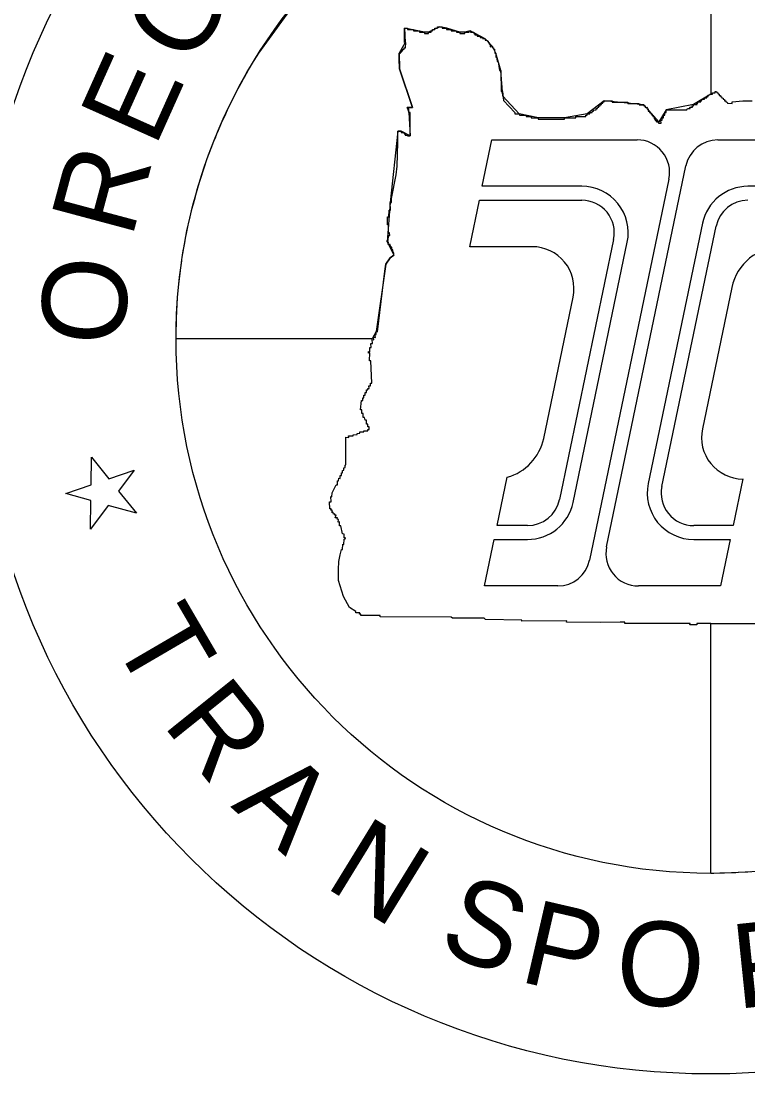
# Model space of a CAD drawing. Extents: x -1.2 to 17.3, y -1 to 2.5.
# Drawn here: x 16.5114 to 16.5609, y 1.8417 to 1.9133 of the extents above; entities that cross this region are included whole.
import ezdxf

# ---------------------------------------------------------------- set-up
doc = ezdxf.new("R2010")
doc.units = 0
doc.layers.add('P_ODOT_PLAN_TBlock', color=7, linetype='Continuous')

msp = doc.modelspace()

# ---------------------------------------------------------------- linework, layer by layer
at = {"layer": 'P_ODOT_PLAN_TBlock'}
for p, q in [((16.542797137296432, 1.9020324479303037), (16.543455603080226, 1.905192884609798)), ((16.543455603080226, 1.905192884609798), (16.55332512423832, 1.905192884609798)), ((16.55881333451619, 1.905192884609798), (16.57758831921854, 1.905192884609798)), ((16.5512484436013, 1.877516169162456), (16.55664756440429, 1.903431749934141)), ((16.549563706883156, 1.9020324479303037), (16.542797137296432, 1.9020324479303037)), ((16.55549089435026, 1.9025294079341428), (16.550092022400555, 1.8766138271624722)), ((16.57692985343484, 1.9020324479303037), (16.56086264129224, 1.9020324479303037)), ((16.541941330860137, 1.8979238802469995), (16.54259979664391, 1.901084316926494)), ((16.54259979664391, 1.901084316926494), (16.549563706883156, 1.901084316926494)), ((16.55776864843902, 1.8995165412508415), (16.554081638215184, 1.8818180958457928)), ((16.555009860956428, 1.8816247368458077), (16.558697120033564, 1.8993231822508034)), ((16.55172947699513, 1.898420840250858), (16.5480424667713, 1.8807223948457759)), ((16.54619099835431, 1.8979238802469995), (16.541941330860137, 1.8979238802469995)), ((16.54619099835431, 1.8979238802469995), (16.54619099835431, 1.8979238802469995)), ((16.548970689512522, 1.8805290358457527), (16.552657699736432, 1.8982274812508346)), ((16.559765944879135, 1.8951563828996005), (16.557763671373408, 1.8855461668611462)), ((16.546973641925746, 1.8848891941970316), (16.54897566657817, 1.8944994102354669)), ((16.54380175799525, 1.8789612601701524), (16.544486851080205, 1.8822498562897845)), ((16.56051573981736, 1.8821284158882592), (16.559855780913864, 1.8789612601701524)), ((16.54587669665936, 1.8789612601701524), (16.54380175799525, 1.8789612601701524)), ((16.559855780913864, 1.8789612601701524), (16.557175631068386, 1.8789612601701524)), ((16.542945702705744, 1.8748526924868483), (16.54360416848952, 1.8780131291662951)), ((16.54360416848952, 1.8780131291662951), (16.54587669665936, 1.8780131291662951)), ((16.557175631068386, 1.8780131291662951), (16.559658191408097, 1.8780131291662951)), ((16.559658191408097, 1.8780131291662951), (16.558999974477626, 1.8748526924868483)), ((16.547926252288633, 1.8748526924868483), (16.542945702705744, 1.8748526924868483)), ((16.558999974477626, 1.8748526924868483), (16.553414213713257, 1.8748526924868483))]:
    msp.add_line(p, q, dxfattribs=at)
for points in [[(16.558333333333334, 1.9280242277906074), (16.558340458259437, 1.9083075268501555), (16.55715661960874, 1.9075933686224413), (16.555301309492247, 1.907231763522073), (16.554808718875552, 1.9064186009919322), (16.55379082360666, 1.9075853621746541), (16.551086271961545, 1.9078535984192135), (16.549935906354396, 1.9069537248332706), (16.548390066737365, 1.906684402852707), (16.546631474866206, 1.906685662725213), (16.545317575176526, 1.9069556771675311), (16.544204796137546, 1.9081749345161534), (16.544048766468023, 1.909918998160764), (16.543716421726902, 1.9110841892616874), (16.543482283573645, 1.911534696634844), (16.543004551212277, 1.9120731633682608), (16.541985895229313, 1.9126121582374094), (16.541606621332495, 1.9125223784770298), (16.541269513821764, 1.9125228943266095), (16.54037756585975, 1.9127918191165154), (16.539908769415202, 1.9128805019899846), (16.539145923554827, 1.9125227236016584), (16.538874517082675, 1.912523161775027), (16.537498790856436, 1.9127917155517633), (16.537554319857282, 1.9118050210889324), (16.537149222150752, 1.91108416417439), (16.537162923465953, 1.9100124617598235), (16.53806055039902, 1.907396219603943), (16.53770219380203, 1.90740352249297), (16.53779376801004, 1.9070446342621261), (16.53789920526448, 1.9054619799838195), (16.537282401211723, 1.9057848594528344), (16.53706220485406, 1.9057864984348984), (16.53653976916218, 1.9009404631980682), (16.5363322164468, 1.8982467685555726), (16.536781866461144, 1.8973430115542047), (16.536536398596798, 1.8971729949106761), (16.53624057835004, 1.8967322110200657), (16.535578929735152, 1.8921601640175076), (16.535321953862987, 1.8916666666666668), (16.521975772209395, 1.8916666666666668), (16.521975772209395, 1.8917899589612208), (16.521975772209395, 1.8920190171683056), (16.52199708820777, 1.892908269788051), (16.522013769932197, 1.8933275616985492), (16.52207953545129, 1.8944684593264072), (16.522187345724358, 1.8956279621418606), (16.52220294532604, 1.8958493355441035), (16.522363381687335, 1.8969587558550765), (16.52237663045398, 1.8970506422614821), (16.52237641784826, 1.8970513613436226), (16.522377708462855, 1.8970612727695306), (16.522399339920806, 1.8972002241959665), (16.522422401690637, 1.8973471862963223), (16.522470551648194, 1.8976423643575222), (16.52250590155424, 1.8978507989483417), (16.52256440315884, 1.8981817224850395), (16.52262636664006, 1.8985126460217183), (16.52270836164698, 1.8989273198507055), (16.522805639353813, 1.8993889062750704), (16.522908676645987, 1.8998504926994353), (16.523057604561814, 1.9004698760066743), (16.523152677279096, 1.9008418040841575), (16.523288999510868, 1.9013495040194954), (16.52342181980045, 1.9018149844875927), (16.523506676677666, 1.9021053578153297), (16.523507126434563, 1.9021068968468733), (16.523511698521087, 1.9021225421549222), (16.52352697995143, 1.9021732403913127), (16.52365660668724, 1.9025931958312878), (16.52386040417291, 1.903220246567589), (16.524101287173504, 1.9039154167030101), (16.52436241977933, 1.9046174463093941), (16.52455419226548, 1.9051142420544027), (16.5246699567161, 1.9054015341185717), (16.524689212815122, 1.905448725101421), (16.524704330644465, 1.9054855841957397), (16.524716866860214, 1.9055160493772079), (16.52472379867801, 1.905532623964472), (16.52472475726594, 1.9055349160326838), (16.52473018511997, 1.905548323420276), (16.52475543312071, 1.905609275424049), (16.524809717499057, 1.9057380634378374), (16.52507671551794, 1.9063590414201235), (16.525222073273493, 1.9066838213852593), (16.525304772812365, 1.9068586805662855), (16.525351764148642, 1.90696597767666), (16.525530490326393, 1.9073454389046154), (16.525767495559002, 1.9078321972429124), (16.526094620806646, 1.9084750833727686), (16.526393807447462, 1.9090371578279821), (16.526564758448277, 1.9093479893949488), (16.5266219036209, 1.9094502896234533), (16.5269050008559, 1.9099459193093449), (16.527012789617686, 1.910130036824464), (16.527131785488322, 1.9103304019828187), (16.527290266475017, 1.9105928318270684), (16.527434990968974, 1.9108280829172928), (16.527597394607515, 1.9110876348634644), (16.530252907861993, 1.9147612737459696)], [(16.565283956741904, 1.8722887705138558), (16.558339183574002, 1.8723013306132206), (16.5573768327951, 1.8722998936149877), (16.557384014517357, 1.8721993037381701), (16.55691720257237, 1.8722036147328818), (16.556928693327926, 1.8722998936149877), (16.552485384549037, 1.872296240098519), (16.552495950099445, 1.872386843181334), (16.552171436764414, 1.8723853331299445), (16.55081865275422, 1.8723699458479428), (16.548535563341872, 1.872381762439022), (16.548543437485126, 1.872472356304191), (16.545484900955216, 1.8724605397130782), (16.54549839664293, 1.8725235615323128), (16.54301604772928, 1.8725617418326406), (16.54293191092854, 1.872662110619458), (16.540771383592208, 1.872656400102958), (16.540690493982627, 1.8727347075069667), (16.535848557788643, 1.8727490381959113), (16.535847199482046, 1.8728476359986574), (16.534550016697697, 1.8728428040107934), (16.534551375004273, 1.8729363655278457), (16.534457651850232, 1.872925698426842), (16.53446308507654, 1.8730181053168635), (16.534202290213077, 1.8730208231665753), (16.534202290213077, 1.8731105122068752), (16.533764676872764, 1.8733880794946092), (16.533369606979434, 1.874138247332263), (16.533030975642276, 1.8752308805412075), (16.533022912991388, 1.875977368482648), (16.533037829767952, 1.8765144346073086), (16.533131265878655, 1.8769719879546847), (16.53322470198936, 1.8773311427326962), (16.53329704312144, 1.877324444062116), (16.533310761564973, 1.8776902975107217), (16.533377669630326, 1.8776793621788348), (16.53339927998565, 1.8780469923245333), (16.533466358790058, 1.878049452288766), (16.533492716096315, 1.8781330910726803), (16.533396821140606, 1.8781330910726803), (16.533401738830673, 1.8783864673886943), (16.533300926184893, 1.8784012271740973), (16.533190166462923, 1.878942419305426), (16.533096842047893, 1.878937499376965), (16.533094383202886, 1.879205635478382), (16.53300094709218, 1.8792031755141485), (16.533018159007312, 1.8793802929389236), (16.532922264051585, 1.8793876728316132), (16.532946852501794, 1.8794836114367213), (16.5327998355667, 1.8794820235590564), (16.532858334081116, 1.8796631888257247), (16.53276981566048, 1.8796582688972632), (16.53276612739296, 1.8797492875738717), (16.53267392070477, 1.879736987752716), (16.53266900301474, 1.8798624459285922), (16.532585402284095, 1.8798353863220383), (16.5325976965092, 1.8800125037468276), (16.532501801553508, 1.8800149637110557), (16.53251901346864, 1.8801035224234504), (16.532425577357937, 1.8801059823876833), (16.532420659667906, 1.880568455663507), (16.53251409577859, 1.8805782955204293), (16.5324993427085, 1.8809325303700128), (16.53257949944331, 1.880915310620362), (16.53259277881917, 1.8811760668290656), (16.532863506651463, 1.8817372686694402), (16.53295679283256, 1.8817317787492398), (16.532953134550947, 1.8819952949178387), (16.533026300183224, 1.8820044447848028), (16.53303727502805, 1.8821801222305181), (16.53312690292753, 1.8821709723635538), (16.53313604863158, 1.8823649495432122), (16.53321470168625, 1.8823576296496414), (16.53321470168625, 1.8825387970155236), (16.533302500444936, 1.88254428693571), (16.533304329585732, 1.882716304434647), (16.533393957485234, 1.8827298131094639), (16.533393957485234, 1.8828919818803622), (16.533481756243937, 1.882908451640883), (16.533481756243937, 1.8830731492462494), (16.533526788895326, 1.8830873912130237), (16.533531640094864, 1.884972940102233), (16.53371356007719, 1.8849559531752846), (16.533701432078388, 1.8850603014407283), (16.5340302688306, 1.8850576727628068), (16.534024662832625, 1.885141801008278), (16.53429188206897, 1.8851474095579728), (16.53429188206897, 1.8852296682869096), (16.534475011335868, 1.8852371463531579), (16.534475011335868, 1.8853268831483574), (16.53474409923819, 1.885325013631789), (16.53473849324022, 1.8854128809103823), (16.535010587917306, 1.8854091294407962), (16.535012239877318, 1.8855000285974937), (16.535103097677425, 1.8854967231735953), (16.535096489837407, 1.885671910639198), (16.53501389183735, 1.8856768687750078), (16.535016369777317, 1.8858528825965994), (16.534924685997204, 1.8858570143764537), (16.534918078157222, 1.8861206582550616), (16.53484108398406, 1.8861265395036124), (16.534778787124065, 1.886300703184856), (16.534694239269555, 1.8863068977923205), (16.534695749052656, 1.8865735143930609), (16.534606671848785, 1.8865735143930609), (16.534609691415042, 1.886842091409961), (16.534519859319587, 1.8868384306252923), (16.534588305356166, 1.8874713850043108), (16.53467060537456, 1.887475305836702), (16.53466864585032, 1.8876537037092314), (16.53475486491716, 1.8876517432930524), (16.53473898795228, 1.8878349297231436), (16.534839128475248, 1.8878305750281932), (16.534836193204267, 1.8880108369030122), (16.53492339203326, 1.8880094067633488), (16.53492339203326, 1.8881938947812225), (16.53500630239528, 1.8881967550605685), (16.535013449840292, 1.8882811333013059), (16.535097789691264, 1.8882797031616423), (16.535092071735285, 1.8884599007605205), (16.535194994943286, 1.8884699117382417), (16.535193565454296, 1.8886443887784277), (16.535286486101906, 1.8886458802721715), (16.535219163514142, 1.8901612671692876), (16.53513885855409, 1.8901676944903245), (16.535154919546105, 1.890704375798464), (16.535061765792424, 1.8906947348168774), (16.535064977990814, 1.8907975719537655), (16.535148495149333, 1.8907815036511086), (16.535158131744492, 1.8910643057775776), (16.535241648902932, 1.891061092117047), (16.53522558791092, 1.891334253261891), (16.53532516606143, 1.891340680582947), (16.535321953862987, 1.8916138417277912), (16.53541831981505, 1.8916009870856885), (16.535408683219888, 1.891771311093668), (16.53553447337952, 1.8917616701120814), (16.53550183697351, 1.891964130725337), (16.535583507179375, 1.8919448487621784), (16.535578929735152, 1.8921601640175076), (16.535681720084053, 1.8921312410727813), (16.53617134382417, 1.8962725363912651), (16.53624057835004, 1.8967322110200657), (16.536536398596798, 1.8971729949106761), (16.536781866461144, 1.8973430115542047), (16.536794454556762, 1.897519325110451), (16.53672942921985, 1.8975309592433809), (16.53672410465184, 1.8977035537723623), (16.536649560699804, 1.8977019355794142), (16.53665275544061, 1.897884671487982), (16.536575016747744, 1.897891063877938), (16.536539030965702, 1.89806614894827), (16.536408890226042, 1.8980669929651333), (16.536422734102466, 1.8982425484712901), (16.5363322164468, 1.8982467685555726), (16.536340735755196, 1.8983387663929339), (16.536409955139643, 1.898343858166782), (16.536419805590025, 1.898697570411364), (16.53650340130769, 1.8986986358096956), (16.536500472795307, 1.8988669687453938), (16.536424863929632, 1.898874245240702), (16.536429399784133, 1.899402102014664), (16.536355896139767, 1.8994198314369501), (16.536355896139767, 1.8999486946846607), (16.536435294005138, 1.8999528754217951), (16.53647392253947, 1.9003999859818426), (16.53656275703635, 1.900404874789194), (16.53653976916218, 1.9009404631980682), (16.536630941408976, 1.900938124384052), (16.53663249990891, 1.9012069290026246), (16.536934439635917, 1.9028220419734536), (16.537012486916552, 1.9034096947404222), (16.53705708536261, 1.9050198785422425), (16.53706220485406, 1.9057864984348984), (16.537282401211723, 1.9057848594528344), (16.53728005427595, 1.9056979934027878), (16.537478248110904, 1.9056947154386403), (16.53748152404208, 1.9056127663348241), (16.537560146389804, 1.9056078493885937), (16.537561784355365, 1.9055193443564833), (16.53773213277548, 1.9055209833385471), (16.537727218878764, 1.9054324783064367), (16.53789920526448, 1.9054619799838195), (16.537890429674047, 1.9070446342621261), (16.53779376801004, 1.9070446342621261), (16.53779885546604, 1.9073118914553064), (16.537709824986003, 1.9073169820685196), (16.53770219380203, 1.90740352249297), (16.53806055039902, 1.907396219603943), (16.537162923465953, 1.9100124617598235), (16.537146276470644, 1.9107256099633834), (16.537149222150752, 1.91108416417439), (16.537231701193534, 1.91108416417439), (16.537235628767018, 1.9111725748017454), (16.537320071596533, 1.9111794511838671), (16.537322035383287, 1.911264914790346), (16.53740058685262, 1.9112678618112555), (16.53740156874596, 1.911354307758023), (16.537489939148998, 1.911354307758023), (16.53748895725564, 1.9114439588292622), (16.53757536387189, 1.9114467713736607), (16.537591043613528, 1.9118047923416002), (16.537517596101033, 1.911805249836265), (16.53749932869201, 1.9124328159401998), (16.537498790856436, 1.9127917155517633), (16.53772253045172, 1.9127922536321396), (16.53772468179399, 1.9127018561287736), (16.53812044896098, 1.9126990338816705), (16.538120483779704, 1.9126093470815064), (16.538542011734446, 1.9126126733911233), (16.53853406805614, 1.9125230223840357), (16.538874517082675, 1.912523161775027), (16.538874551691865, 1.9124340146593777), (16.53914616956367, 1.9124341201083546), (16.539145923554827, 1.9125227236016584), (16.539324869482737, 1.9125232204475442), (16.539324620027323, 1.912613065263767), (16.539414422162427, 1.912612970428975), (16.539414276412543, 1.9127033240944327), (16.539582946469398, 1.9127030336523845), (16.539582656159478, 1.912792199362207), (16.539754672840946, 1.9127913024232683), (16.539753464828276, 1.9128805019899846), (16.540064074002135, 1.9128805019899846), (16.540066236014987, 1.912793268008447), (16.54037756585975, 1.9127918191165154), (16.540369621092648, 1.9127028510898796), (16.540693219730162, 1.9127024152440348), (16.540692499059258, 1.912612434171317), (16.541044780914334, 1.912612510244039), (16.541045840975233, 1.9125200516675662), (16.541269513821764, 1.9125228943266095), (16.541271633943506, 1.9124327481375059), (16.54160323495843, 1.9124327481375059), (16.541606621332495, 1.9125223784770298), (16.54185099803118, 1.9125220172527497), (16.541913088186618, 1.9125198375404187), (16.541913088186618, 1.9126104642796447), (16.541985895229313, 1.9126121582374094), (16.5419901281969, 1.9125180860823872), (16.542214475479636, 1.9125215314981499), (16.542214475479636, 1.912435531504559), (16.542291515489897, 1.9124334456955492), (16.542289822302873, 1.9123426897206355), (16.542441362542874, 1.9123411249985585), (16.542452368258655, 1.912250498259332), (16.54267248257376, 1.9122496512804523), (16.54264562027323, 1.9121632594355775), (16.54282596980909, 1.9121633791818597), (16.542822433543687, 1.9120765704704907), (16.543004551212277, 1.9120731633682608), (16.543005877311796, 1.911982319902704), (16.54309516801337, 1.9119829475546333), (16.543188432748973, 1.9118945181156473), (16.543191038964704, 1.911804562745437), (16.543262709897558, 1.9118026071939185), (16.543262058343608, 1.9117084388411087), (16.543335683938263, 1.911713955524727), (16.543335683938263, 1.9115288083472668), (16.543482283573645, 1.911534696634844), (16.543483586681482, 1.9114447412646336), (16.543553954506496, 1.9114440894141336), (16.543553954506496, 1.9113556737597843), (16.543625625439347, 1.9113549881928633), (16.543647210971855, 1.9110848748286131), (16.543716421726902, 1.9110841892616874), (16.54371573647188, 1.9108161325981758), (16.543760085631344, 1.910813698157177), (16.543802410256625, 1.9105483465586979), (16.543874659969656, 1.910501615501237), (16.543970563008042, 1.9099197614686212), (16.544048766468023, 1.909918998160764), (16.544075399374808, 1.9084839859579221), (16.544171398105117, 1.9084839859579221), (16.54423819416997, 1.9078658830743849), (16.545003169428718, 1.9070450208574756), (16.545007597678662, 1.906956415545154), (16.545317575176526, 1.9069556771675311), (16.545319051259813, 1.9068683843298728), (16.545785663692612, 1.906866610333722), (16.54579098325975, 1.906777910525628), (16.54612434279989, 1.906774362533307), (16.546126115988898, 1.906685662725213), (16.546631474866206, 1.906685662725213), (16.546598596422, 1.906592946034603), (16.54834399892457, 1.9065994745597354), (16.548386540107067, 1.9065961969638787), (16.548390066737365, 1.906684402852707), (16.54915769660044, 1.9066926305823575), (16.549155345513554, 1.9067773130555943), (16.54984656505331, 1.9067820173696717), (16.54984303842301, 1.9068725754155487), (16.54993002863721, 1.906867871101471), (16.549935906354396, 1.9069537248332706), (16.55010829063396, 1.9069607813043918), (16.55010753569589, 1.9070431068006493), (16.55027446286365, 1.907047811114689), (16.55028393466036, 1.907135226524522), (16.55036718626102, 1.9071373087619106), (16.55036718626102, 1.9072226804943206), (16.550548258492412, 1.9072237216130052), (16.550546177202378, 1.9073163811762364), (16.550632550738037, 1.9073163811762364), (16.550633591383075, 1.907401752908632), (16.55073261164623, 1.9074152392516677), (16.55072724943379, 1.907493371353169), (16.550814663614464, 1.9074964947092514), (16.550810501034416, 1.907587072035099), (16.55090624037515, 1.907593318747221), (16.55090624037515, 1.9076776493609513), (16.55099219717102, 1.9076807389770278), (16.550992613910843, 1.9077651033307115), (16.55107815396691, 1.9077681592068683), (16.551086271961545, 1.9078535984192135), (16.551626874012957, 1.9078482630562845), (16.55162102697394, 1.9077634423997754), (16.55269688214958, 1.9077634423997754), (16.552692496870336, 1.9076713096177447), (16.553452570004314, 1.9076713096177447), (16.55345779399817, 1.9075791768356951), (16.55379082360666, 1.9075853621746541), (16.553785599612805, 1.9074952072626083), (16.553884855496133, 1.9074991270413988), (16.553871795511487, 1.9073998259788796), (16.554000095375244, 1.907406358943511), (16.553997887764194, 1.9073174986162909), (16.55408288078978, 1.907312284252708), (16.55408075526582, 1.9071358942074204), (16.55416456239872, 1.9071358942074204), (16.554162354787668, 1.9070457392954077), (16.554248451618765, 1.9070470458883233), (16.554253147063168, 1.9069580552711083), (16.55432682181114, 1.9069477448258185), (16.554330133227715, 1.9068641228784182), (16.554410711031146, 1.90687326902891), (16.554406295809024, 1.9067818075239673), (16.55449239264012, 1.9067674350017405), (16.554489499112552, 1.9066248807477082), (16.554557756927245, 1.9065984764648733), (16.554565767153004, 1.9065198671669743), (16.554647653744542, 1.906510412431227), (16.554642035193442, 1.906414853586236), (16.554808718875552, 1.9064186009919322), (16.55478576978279, 1.9063284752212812), (16.554969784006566, 1.906336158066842), (16.55493525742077, 1.906509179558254), (16.555037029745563, 1.9065288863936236), (16.55502718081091, 1.9066881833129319), (16.555117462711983, 1.9066947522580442), (16.555117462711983, 1.9068721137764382), (16.555209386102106, 1.90687868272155), (16.555211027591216, 1.907051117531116), (16.55530295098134, 1.9070593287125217), (16.555301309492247, 1.907231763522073), (16.556704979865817, 1.9072261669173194), (16.55674253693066, 1.907328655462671), (16.556928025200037, 1.9073220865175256), (16.55691981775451, 1.90740584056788), (16.557098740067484, 1.9074156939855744), (16.557067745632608, 1.9074987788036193), (16.55715472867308, 1.907503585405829), (16.55715661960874, 1.9075933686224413), (16.55740811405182, 1.90759147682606), (16.55739298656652, 1.9076690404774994), (16.557462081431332, 1.9076860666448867), (16.55745549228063, 1.9077730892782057), (16.55765204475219, 1.9077749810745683), (16.55765393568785, 1.9078487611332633), (16.557729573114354, 1.9078698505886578), (16.557731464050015, 1.9079433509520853), (16.55789975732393, 1.9079647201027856), (16.557903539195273, 1.9080379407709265), (16.55805894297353, 1.9080398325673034), (16.558068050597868, 1.9081249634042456), (16.55814746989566, 1.9081400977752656), (16.55815881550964, 1.9082384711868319), (16.558347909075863, 1.9083103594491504), (16.55845374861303, 1.9083072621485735), (16.5584455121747, 1.9083946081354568), (16.558631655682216, 1.9083979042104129), (16.558628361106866, 1.9084836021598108), (16.558718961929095, 1.9084852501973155), (16.558737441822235, 1.9084106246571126), (16.558816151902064, 1.9083929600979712), (16.558828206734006, 1.9083141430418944), (16.558913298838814, 1.9083084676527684), (16.55890573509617, 1.9082157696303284), (16.5589927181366, 1.9082119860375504), (16.55899082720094, 1.9081325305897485), (16.55907213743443, 1.9081230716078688), (16.55908537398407, 1.9080398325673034), (16.559185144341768, 1.9080360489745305), (16.559174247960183, 1.9079603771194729), (16.559267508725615, 1.9079471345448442), (16.559270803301, 1.9078563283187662), (16.559356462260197, 1.9078544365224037), (16.559358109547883, 1.9077749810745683), (16.559443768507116, 1.907765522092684), (16.55947376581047, 1.9076767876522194), (16.55979793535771, 1.9076744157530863), (16.55979299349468, 1.9077683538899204), (16.560514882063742, 1.9078539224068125), (16.561149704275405, 1.9078539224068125)], [(16.561070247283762, 1.855412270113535), (16.56085035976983, 1.8553963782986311), (16.56072834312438, 1.8553880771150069), (16.56068176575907, 1.8553850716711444), (16.560213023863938, 1.855358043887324), (16.560048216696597, 1.8553495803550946), (16.559783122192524, 1.8553380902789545), (16.559273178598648, 1.855320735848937), (16.558955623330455, 1.8553142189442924), (16.55854567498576, 1.8553095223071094), (16.5583996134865, 1.8553091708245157), (16.558333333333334, 1.8553091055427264), (16.558333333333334, 1.8723013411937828), (16.565283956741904, 1.8722887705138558)]]:
    msp.add_lwpolyline(points, dxfattribs=at)
msp.add_lwpolyline([(16.514479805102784, 1.8811399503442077), (16.516203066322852, 1.88173331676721), (16.516226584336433, 1.88360265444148), (16.51739599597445, 1.8821440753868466), (16.519119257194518, 1.8827374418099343), (16.518066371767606, 1.8813079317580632), (16.519276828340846, 1.8797981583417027), (16.517351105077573, 1.8803368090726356), (16.51616524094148, 1.8787267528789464), (16.516189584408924, 1.880661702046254)], close=True, dxfattribs=at)
for radius in [0.050000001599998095, 0.036357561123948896]:
    msp.add_circle((16.558333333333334, 1.8916666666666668), radius, dxfattribs=at)
for centre, radius, start, end in [((16.553325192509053, 1.9029804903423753), 0.002212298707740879, 348.23180555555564, 90.00000000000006), ((16.558813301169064, 1.9029804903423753), 0.002212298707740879, 90.00000000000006, 168.2318055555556), ((16.549563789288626, 1.8988719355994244), 0.003160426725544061, 348.23183055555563, 90.00000000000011), ((16.56086275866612, 1.8988719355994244), 0.003160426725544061, 90.00000000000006, 168.23180000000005), ((16.549563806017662, 1.8988719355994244), 0.002212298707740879, 348.23171111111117, 90.00000000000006), ((16.560862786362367, 1.8988719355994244), 0.002212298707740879, 90.00000000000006, 168.23184166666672), ((16.54619107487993, 1.8950794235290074), 0.002844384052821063, 348.2317944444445, 90.00000000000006), ((16.563169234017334, 1.894447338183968), 0.00347646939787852, 90.00000000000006, 168.2318944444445), ((16.5605483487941, 1.884966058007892), 0.0028443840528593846, 168.23179444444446, 269.30883611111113), ((16.543570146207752, 1.8855981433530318), 0.0034764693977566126, 285.46915555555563, 348.23171111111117), ((16.55717563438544, 1.8811735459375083), 0.003160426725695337, 168.23183055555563, 270.0000000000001), ((16.557175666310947, 1.8811735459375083), 0.0022122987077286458, 168.2317944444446, 270.00000000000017), ((16.545876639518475, 1.8811735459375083), 0.0022122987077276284, 270.00000000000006, 348.2317722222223), ((16.54587666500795, 1.8811735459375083), 0.003160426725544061, 270.00000000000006, 348.2318), ((16.55341428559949, 1.877064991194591), 0.0022122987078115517, 168.2317694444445, 270.00000000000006), ((16.547926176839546, 1.877064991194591), 0.00221229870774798, 270.00000000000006, 348.23175555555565)]:
    msp.add_arc(centre, radius, start, end, dxfattribs=at)

# ---------------------------------------------------------------- texts
for s, height, rotation, p in [('G', 0.005738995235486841, 57.37401345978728, (16.52285313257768, 1.9100269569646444)), ('E', 0.005738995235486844, 65.85624536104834, (16.520533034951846, 1.9045927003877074)), ('R', 0.005738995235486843, 75.01818084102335, (16.518957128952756, 1.898409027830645)), ('O', 0.005738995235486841, 85.57858690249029, (16.518388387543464, 1.8910782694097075)), ('T', 0.005738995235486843, 300.2743684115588, (16.517532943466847, 1.8712683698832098)), ('R', 0.005738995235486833, 308.7800383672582, (16.52099875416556, 1.8654580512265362)), ('A', 0.005738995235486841, 317.94197384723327, (16.525648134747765, 1.8598478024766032)), ('N', 0.005738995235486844, 328.40862769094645, (16.53197230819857, 1.8544395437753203)), ('S', 0.005738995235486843, 339.5081090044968, (16.539632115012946, 1.8500610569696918)), ('P', 0.005738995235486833, 346.9746918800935, (16.545197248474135, 1.8479836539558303)), ('O', 0.005738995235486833, 355.3787969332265, (16.551722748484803, 1.8465328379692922)), ('R', 0.005738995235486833, 5.939202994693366, (16.56010648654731, 1.846085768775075))]:
    msp.add_text(s, height=height, rotation=rotation, dxfattribs=at).set_placement(p)

doc.saveas('drawing.dxf')
